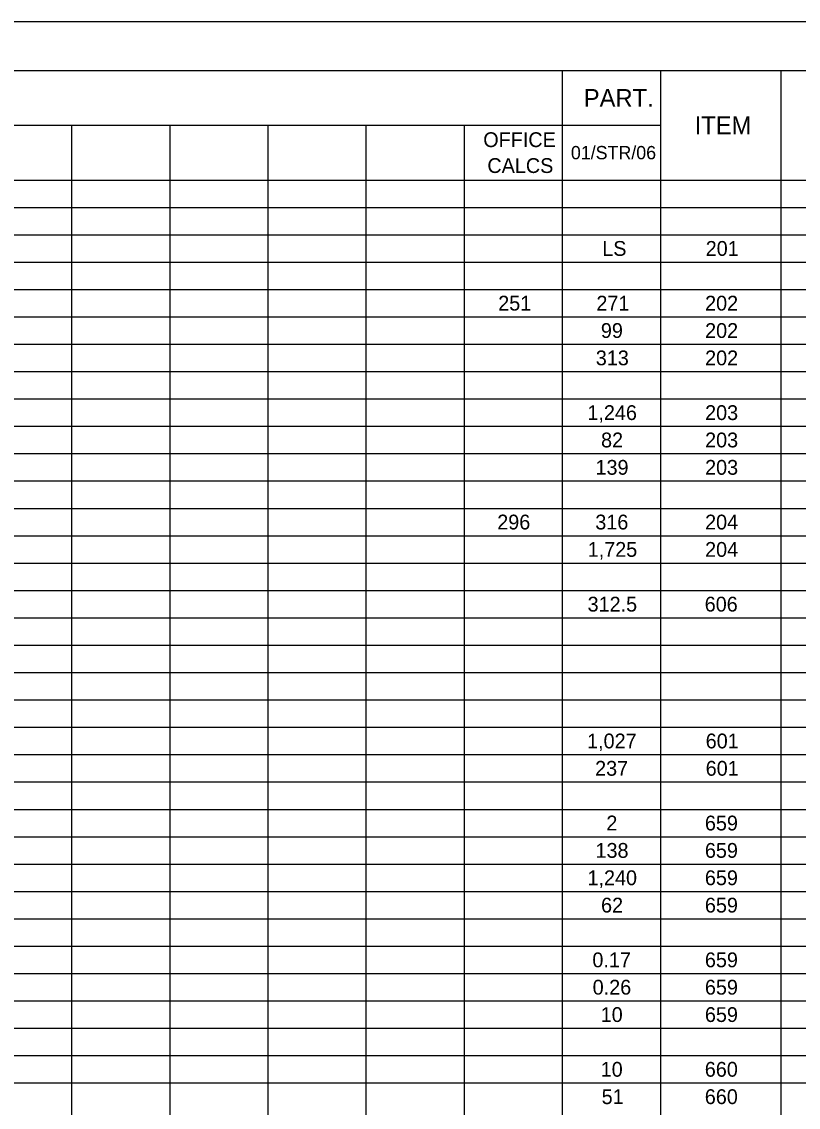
# Model space of a CAD drawing. Extents: x 0 to 34, y 0 to 22.
# Drawn here: x 9.03 to 16.98, y 10.89 to 22 of the extents above; entities that cross this region are included whole.
import ezdxf

# ---------------------------------------------------------------- set-up
doc = ezdxf.new("R2010")
doc.units = 0
for name, color, linetype in [('SH_Border', 7, 'Continuous'), ('SH_Cut_Line', 7, 'Continuous'), ('SH_Text', 7, 'Continuous')]:
    doc.layers.add(name, color=color, linetype=linetype)

msp = doc.modelspace()

# ---------------------------------------------------------------- linework, layer by layer
at = {"layer": 'SH_Border'}
msp.add_lwpolyline([(1.5, 21.5), (33.5, 21.5), (33.5, 0.5), (1.5, 0.5)], close=True, dxfattribs=at)
at = {"layer": 'SH_Cut_Line'}
msp.add_lwpolyline([(0, 0), (34, 0), (34, 22), (0, 22)], close=True, dxfattribs=at)
at = {"layer": 'SH_Text'}
for p, q in [((1.5, 21.5), (32, 21.5)), ((14.56, 21.5), (14.56, 0.5)), ((15.564, 21.5), (15.564, 0.5)), ((16.799, 21.5), (16.799, 0.5)), ((1.5, 20.94), (15.564, 20.94)), ((9.537, 20.94), (9.537, 0.5)), ((10.541, 20.94), (10.541, 0.5)), ((11.546, 20.94), (11.546, 0.5)), ((12.55, 20.94), (12.55, 0.5)), ((13.555, 20.94), (13.555, 0.5)), ((1.5, 20.38), (32, 20.38)), ((1.5, 20.1), (32, 20.1)), ((1.5, 19.82), (32, 19.82)), ((1.5, 19.54), (32, 19.54)), ((1.5, 19.26), (32, 19.26)), ((1.5, 18.98), (32, 18.98)), ((1.5, 18.7), (32, 18.7)), ((1.5, 18.42), (32, 18.42)), ((1.5, 18.14), (32, 18.14)), ((1.5, 17.86), (32, 17.86)), ((1.5, 17.58), (32, 17.58)), ((1.5, 17.3), (32, 17.3)), ((1.5, 17.02), (32, 17.02)), ((1.5, 16.74), (32, 16.74)), ((1.5, 16.46), (32, 16.46)), ((1.5, 16.18), (32, 16.18)), ((1.5, 15.9), (32, 15.9)), ((1.5, 15.62), (32, 15.62)), ((1.5, 15.34), (32, 15.34)), ((1.5, 15.06), (32, 15.06)), ((1.5, 14.78), (32, 14.78)), ((1.5, 14.5), (32, 14.5)), ((1.5, 14.22), (32, 14.22)), ((1.5, 13.94), (32, 13.94)), ((1.5, 13.66), (32, 13.66)), ((1.5, 13.38), (32, 13.38)), ((1.5, 13.1), (32, 13.1)), ((1.5, 12.82), (32, 12.82)), ((1.5, 12.54), (32, 12.54)), ((1.5, 12.26), (32, 12.26)), ((1.5, 11.98), (32, 11.98)), ((1.5, 11.7), (32, 11.7)), ((1.5, 11.42), (32, 11.42)), ((1.5, 11.14), (32, 11.14))]:
    msp.add_line(p, q, dxfattribs=at)

# ---------------------------------------------------------------- texts
for s, height, p in [('PART.', 0.1818, (14.78, 21.129)), ('ITEM', 0.1818, (15.915, 20.849)), ('OFFICE ', 0.1515, (13.751, 20.717)), ('01/STR/06', 0.1364, (14.648, 20.592)), ('CALCS', 0.1515, (13.793, 20.452)), ('LS', 0.1515, (14.969, 19.604)), ('201', 0.1515, (16.028, 19.604)), ('251', 0.1515, (13.904, 19.044)), ('271', 0.1515, (14.909, 19.044)), ('202', 0.1515, (16.022, 19.044)), ('99', 0.1515, (14.955, 18.764)), ('202', 0.1515, (16.022, 18.764)), ('313', 0.1515, (14.903, 18.484)), ('202', 0.1515, (16.022, 18.484)), ('1,246', 0.1515, (14.817, 17.924)), ('203', 0.1515, (16.022, 17.924)), ('82', 0.1515, (14.957, 17.644)), ('203', 0.1515, (16.022, 17.644)), ('139', 0.1515, (14.9, 17.364)), ('203', 0.1515, (16.022, 17.364)), ('296', 0.1515, (13.894, 16.804)), ('316', 0.1515, (14.898, 16.804)), ('204', 0.1515, (16.022, 16.804)), ('1,725', 0.1515, (14.82, 16.524)), ('204', 0.1515, (16.022, 16.524)), ('312.5', 0.1515, (14.819, 15.964)), ('606', 0.1515, (16.018, 15.964)), ('1,027', 0.1515, (14.814, 14.564)), ('601', 0.1515, (16.028, 14.564)), ('237', 0.1515, (14.896, 14.284)), ('601', 0.1515, (16.028, 14.284)), ('2', 0.152, (15.011, 13.724)), ('659', 0.1515, (16.02, 13.724)), ('138', 0.1515, (14.9, 13.444)), ('659', 0.1515, (16.02, 13.444)), ('1,240', 0.1515, (14.818, 13.164)), ('659', 0.1515, (16.02, 13.164)), ('62', 0.1515, (14.957, 12.884)), ('659', 0.1515, (16.02, 12.884)), ('0.17', 0.1515, (14.868, 12.324)), ('659', 0.1515, (16.02, 12.324)), ('0.26', 0.1515, (14.871, 12.044)), ('659', 0.1515, (16.02, 12.044)), ('10', 0.1515, (14.953, 11.764)), ('659', 0.1515, (16.02, 11.764)), ('10', 0.1515, (14.953, 11.204)), ('660', 0.1515, (16.019, 11.204)), ('51', 0.1515, (14.963, 10.924)), ('660', 0.1515, (16.019, 10.924))]:
    msp.add_text(s, height=height, dxfattribs=at).set_placement(p)

doc.saveas('drawing.dxf')
